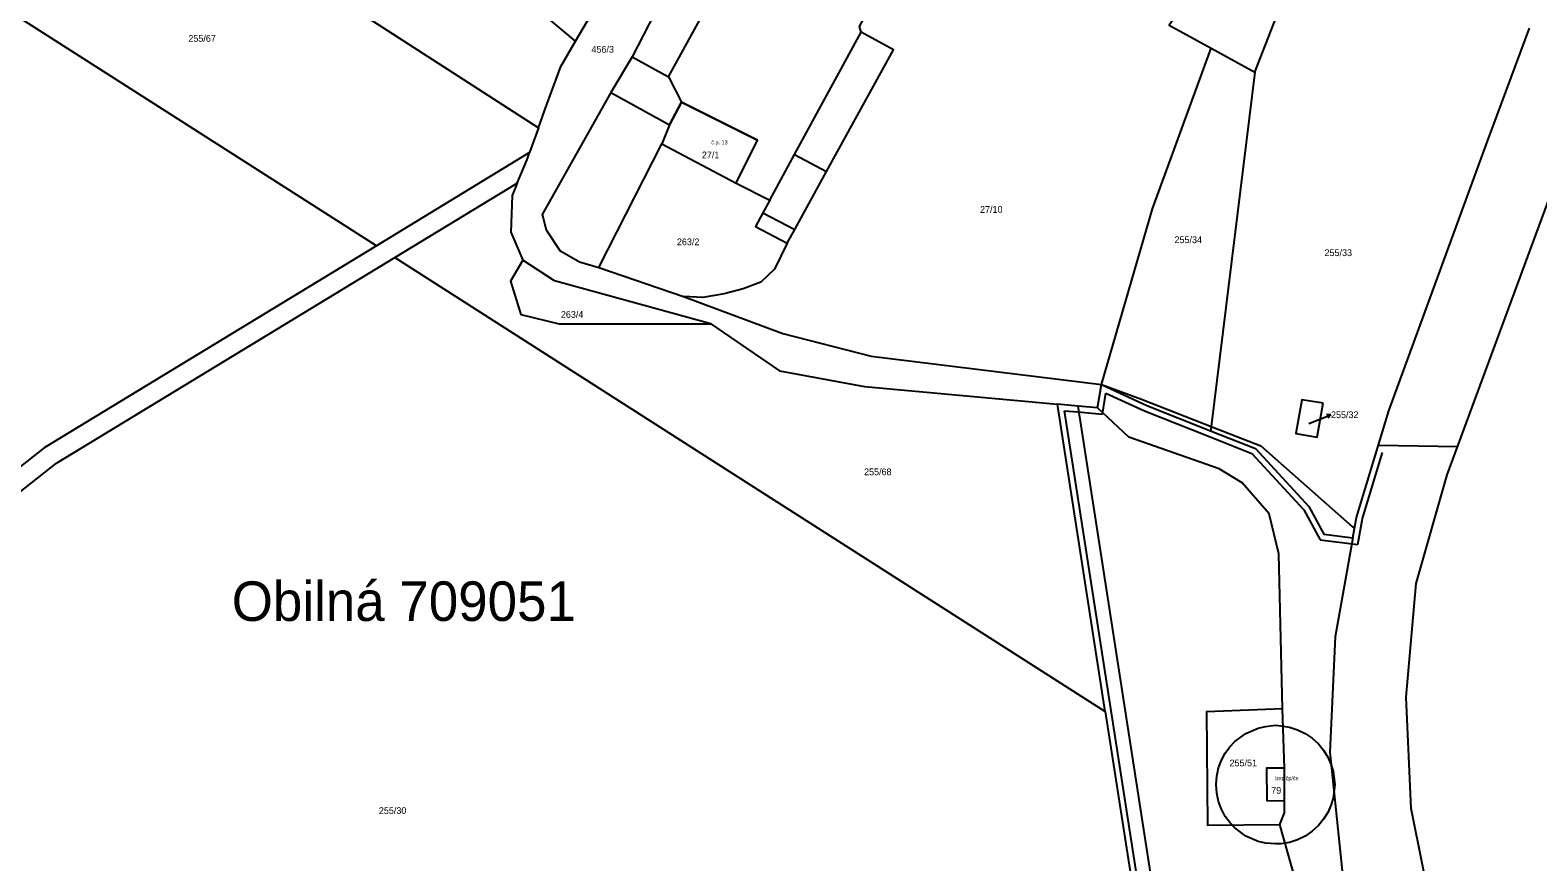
# Model space of a CAD drawing. Extents: x -882150 to -879379, y -1022570 to -1019819.
# Drawn here: x -880738 to -880356.9, y -1021575.9 to -1021365.7 of the extents above; entities that cross this region are included whole.
import ezdxf

# ---------------------------------------------------------------- set-up
doc = ezdxf.new("R2010")
doc.units = 0
for name, color, linetype in [('Definiční body', 7, 'Continuous'), ('Hranice parcel', 7, 'Continuous'), ('Parcelní čísla', 7, 'Continuous'), ('Polygon budovy', 7, 'Continuous'), ('Pop  PČ popisy', 7, 'Continuous'), ('Vnitřní kresba', 7, 'Continuous')]:
    doc.layers.add(name, color=color, linetype=linetype)

msp = doc.modelspace()

# ---------------------------------------------------------------- linework, layer by layer
at = {"layer": 'Hranice parcel'}
for p, q in [((-880600.19, -1021368.5), (-880660.06, -1021317.87)), ((-880600.19, -1021368.5), (-880583.69, -1021340.23)), ((-880428.51, -1021376.32), (-880419.38, -1021353.05)), ((-880439.53, -1021370.25), (-880428.51, -1021376.32)), ((-880428.51, -1021376.32), (-880439.5, -1021465.87)), ((-880609.55, -1021390.4), (-880611.8, -1021396.64)), ((-880611.8, -1021396.64), (-880650.52, -1021420.19)), ((-880645.83, -1021423.18), (-880614.91, -1021404.39)), ((-880468.25, -1021461.16), (-880467.26, -1021455.29)), ((-880467.26, -1021455.29), (-880455.76, -1021460.57)), ((-880473.1, -1021460.72), (-880478.38, -1021460.24)), ((-880466.28, -1021537.91), (-880478.38, -1021460.24)), ((-880468.25, -1021461.16), (-880473.1, -1021460.72)), ((-880460.36, -1021468.6), (-880468.25, -1021461.16)), ((-880455.76, -1021460.57), (-880439.64, -1021466.97)), ((-880439.5, -1021465.87), (-880439.64, -1021466.97)), ((-880403.68, -1021494.04), (-880403.27, -1021491.7)), ((-880420.99, -1021552.23), (-880421.46, -1021537.21)), ((-880421, -1021560.46), (-880420.99, -1021552.23))]:
    msp.add_line(p, q, dxfattribs=at)
for points in [[(-880383.32, -1021590.53), (-880388.97, -1021562.43), (-880390.19, -1021534.27), (-880387.73, -1021505.59), (-880379.83, -1021478.12), (-880354.56, -1021409.73), (-880325.92, -1021331.12), (-880321.65, -1021310.18), (-880321.88, -1021279.76), (-880330.68, -1021225.65), (-880330.04, -1021210.18), (-880313.87, -1021148.79), (-880301.09, -1021117.72), (-880281.33, -1021095.35), (-880255.32, -1021084.31), (-880230.68, -1021082.99), (-880217.42, -1021078.67), (-880186.94, -1021050.63), (-880171.67, -1021029), (-880165.07, -1021009.24), (-880163.83, -1020993.67)], [(-880852.86, -1021290.89), (-880665.52, -1021354.25), (-880609.55, -1021390.4)], [(-880650.52, -1021420.19), (-880751.74, -1021355.5), (-880852.86, -1021290.89)], [(-880546.66, -1021419.56), (-880544.76, -1021416.1), (-880536.71, -1021401.44), (-880519.81, -1021370.66), (-880528.01, -1021366.19), (-880528.37, -1021364.81), (-880521.3, -1021351.55), (-880551.77, -1021336.02)], [(-880427.85, -1021339.96), (-880435.17, -1021343.19), (-880450.1, -1021364.49), (-880439.53, -1021370.25)], [(-880572.87, -1021347.16), (-880585.84, -1021372.47), (-880591.22, -1021381.45)], [(-880403.27, -1021491.7), (-880402.77, -1021488.9), (-880394.62, -1021461.91), (-880369.65, -1021393.76), (-880359.04, -1021365.24)], [(-880609.55, -1021390.4), (-880608, -1021386.1), (-880603.94, -1021374.93), (-880600.19, -1021368.5)], [(-880467.26, -1021455.29), (-880454.38, -1021410.86), (-880439.53, -1021370.25)], [(-880591.22, -1021381.45), (-880608.58, -1021412.27), (-880608.35, -1021413.24), (-880607.63, -1021416.21), (-880604.16, -1021421.37), (-880599.2, -1021424.29), (-880594.31, -1021425.69), (-880572.86, -1021432.99)], [(-880591.22, -1021381.45), (-880576.42, -1021389.62), (-880578.36, -1021394.48), (-880559.6, -1021404.38), (-880551.1, -1021408.71), (-880552.81, -1021411.85), (-880554.69, -1021415.32), (-880546.66, -1021419.56)], [(-880614.91, -1021404.39), (-880612.44, -1021398.43), (-880611.8, -1021396.64)], [(-880614.91, -1021404.39), (-880616.19, -1021407.47), (-880616.55, -1021416.74), (-880613.47, -1021423.85)], [(-880650.52, -1021420.19), (-880734.5, -1021471.26), (-880791.06, -1021515.8)], [(-880546.66, -1021419.56), (-880549.89, -1021426.1), (-880553.31, -1021429.43), (-880557.81, -1021431.11), (-880562.65, -1021432.4), (-880568.03, -1021433.26), (-880572.86, -1021432.99)], [(-880872.75, -1021653.59), (-880853.95, -1021571.88), (-880731.4, -1021475.19), (-880645.83, -1021423.18)], [(-880645.83, -1021423.18), (-880556.09, -1021480.53), (-880466.28, -1021537.91)], [(-880613.47, -1021423.85), (-880616.65, -1021429.12), (-880614.04, -1021437.55), (-880604.28, -1021439.9), (-880566, -1021439.93)], [(-880566, -1021439.93), (-880605.48, -1021429.1), (-880613.47, -1021423.85)], [(-880572.86, -1021432.99), (-880547.77, -1021442.37), (-880525.48, -1021448.12), (-880467.26, -1021455.29)], [(-880566, -1021439.93), (-880548.61, -1021451.85), (-880527.16, -1021455.82), (-880478.38, -1021460.24)], [(-880533.86, -1022007.05), (-880523.29, -1021950.58), (-880522.43, -1021909.12), (-880520.53, -1021864.27), (-880518.3, -1021819.45), (-880460.57, -1021640.65), (-880455.51, -1021609.22), (-880454.71, -1021579.75), (-880473.1, -1021460.72)], [(-880411.22, -1021459.95), (-880416.58, -1021459.18), (-880418.12, -1021467.65), (-880412.75, -1021468.59), (-880411.22, -1021459.95)], [(-880421.46, -1021537.21), (-880422.44, -1021498.09), (-880424.83, -1021487.94), (-880431.68, -1021480.16), (-880437.46, -1021476.63), (-880460.36, -1021468.6)], [(-880439.64, -1021466.97), (-880428.32, -1021471.47), (-880414.85, -1021486.07), (-880411, -1021493.14), (-880403.68, -1021494.04)], [(-880403.68, -1021494.04), (-880408.13, -1021519.01), (-880409.49, -1021548.16), (-880406.41, -1021578.18), (-880397.35, -1021608.26), (-880377.39, -1021650.23), (-880346.77, -1021685.06), (-880313.96, -1021718.82), (-880296.93, -1021753.52), (-880294.62, -1021788.33), (-880298.33, -1021816.85), (-880311.6, -1021844.17), (-880330.67, -1021863.71), (-880363.25, -1021882.74), (-880382, -1021885.04)], [(-880466.28, -1021537.91), (-880459.65, -1021580.52), (-880460.51, -1021609.07), (-880465.51, -1021639.85), (-880472.9, -1021662.8)], [(-880421.46, -1021537.21), (-880440.7, -1021538.04), (-880440.47, -1021566.64), (-880422.16, -1021566.44)], [(-880420.99, -1021552.23), (-880425.55, -1021552.23), (-880425.42, -1021560.45), (-880421, -1021560.46)], [(-880422.16, -1021566.44), (-880420.98, -1021563.52), (-880421, -1021560.46)], [(-880328.46, -1021721.51), (-880371.01, -1021681.52), (-880393.83, -1021651.84), (-880414.22, -1021594.55), (-880422.16, -1021566.44)]]:
    msp.add_lwpolyline(points, dxfattribs=at)
at = {"layer": 'Polygon budovy'}
for points in [[(-880578.36, -1021394.48), (-880559.6, -1021404.38), (-880554.18, -1021393.55), (-880573.42, -1021383.9), (-880576.42, -1021389.62)], [(-880425.42, -1021560.45), (-880421, -1021560.46), (-880420.99, -1021552.23), (-880425.55, -1021552.23)]]:
    msp.add_lwpolyline(points, close=True, dxfattribs=at)
at = {"layer": 'Pop  PČ popisy'}
for p, q in [((-880414.82, -1021465.09), (-880412.03, -1021464.01)), ((-880412.03, -1021464.01), (-880409.228, -1021462.935)), ((-880409.228, -1021462.935), (-880410.343, -1021462.826)), ((-880409.228, -1021462.935), (-880409.984, -1021463.761))]:
    msp.add_line(p, q, dxfattribs=at)
at = {"layer": 'Vnitřní kresba'}
for p, q in [((-880576.66, -1021377.55), (-880562.99, -1021352.49)), ((-880544.83, -1021397.15), (-880528.01, -1021366.19)), ((-880585.84, -1021372.47), (-880576.66, -1021377.55)), ((-880576.66, -1021377.55), (-880573.42, -1021383.9)), ((-880576.42, -1021389.62), (-880573.42, -1021383.9)), ((-880573.42, -1021383.9), (-880554.18, -1021393.55)), ((-880559.6, -1021404.38), (-880554.18, -1021393.55)), ((-880594.31, -1021425.69), (-880578.36, -1021394.48)), ((-880551.1, -1021408.71), (-880544.83, -1021397.15)), ((-880544.83, -1021397.15), (-880536.71, -1021401.44)), ((-880552.81, -1021411.85), (-880544.76, -1021416.1)), ((-880467.26, -1021455.29), (-880457.12, -1021458.95)), ((-880467, -1021462.78), (-880466.11, -1021457.47)), ((-880466.11, -1021457.47), (-880456.35, -1021461.95)), ((-880458.15, -1021580.43), (-880476.6, -1021461.91)), ((-880476.6, -1021461.91), (-880473.24, -1021462.21)), ((-880473.24, -1021462.21), (-880467, -1021462.78)), ((-880457.12, -1021458.95), (-880439.5, -1021465.87)), ((-880456.35, -1021461.95), (-880440.19, -1021468.36)), ((-880439.5, -1021465.87), (-880426.93, -1021470.81)), ((-880440.19, -1021468.36), (-880429.19, -1021472.74)), ((-880429.19, -1021472.74), (-880416.08, -1021486.95)), ((-880426.93, -1021470.81), (-880403.84, -1021491.19)), ((-880401.29, -1021489.16), (-880396.24, -1021472.46)), ((-880397.23, -1021470.57), (-880377.17, -1021470.93)), ((-880416.08, -1021486.95), (-880411.95, -1021494.54)), ((-880402.45, -1021495.7), (-880401.29, -1021489.16)), ((-880403.84, -1021491.19), (-880403.27, -1021491.7)), ((-880411.95, -1021494.54), (-880402.45, -1021495.7)), ((-880430.75, -1021543.47), (-880427.6, -1021542.11)), ((-880427.6, -1021542.11), (-880425.79, -1021541.68)), ((-880425.79, -1021541.68), (-880423.24, -1021541.41)), ((-880423.24, -1021541.41), (-880421.81, -1021541.53)), ((-880421.81, -1021541.53), (-880419.75, -1021541.88)), ((-880419.75, -1021541.88), (-880417.72, -1021542.53)), ((-880417.72, -1021542.53), (-880415.78, -1021543.47)), ((-880434.79, -1021546.88), (-880433.51, -1021545.52)), ((-880433.51, -1021545.52), (-880430.75, -1021543.47)), ((-880415.78, -1021543.47), (-880414, -1021544.68)), ((-880414, -1021544.68), (-880412.42, -1021546.12)), ((-880412.42, -1021546.12), (-880411.09, -1021547.73)), ((-880437.63, -1021552.2), (-880436.9, -1021550.24)), ((-880436.9, -1021550.24), (-880435.94, -1021548.46)), ((-880435.94, -1021548.46), (-880434.79, -1021546.88)), ((-880411.09, -1021547.73), (-880410.02, -1021549.46)), ((-880410.02, -1021549.46), (-880409.22, -1021551.24)), ((-880438.08, -1021554.29), (-880437.63, -1021552.2)), ((-880409.22, -1021551.24), (-880408.69, -1021553.02)), ((-880408.69, -1021553.02), (-880408.29, -1021556.44)), ((-880438.24, -1021556.41), (-880438.08, -1021554.29)), ((-880438.08, -1021558.59), (-880438.24, -1021556.41)), ((-880408.29, -1021556.44), (-880408.69, -1021559.85)), ((-880437.63, -1021560.67), (-880438.08, -1021558.59)), ((-880436.9, -1021562.63), (-880437.63, -1021560.67)), ((-880409.22, -1021561.64), (-880410.02, -1021563.42)), ((-880408.69, -1021559.85), (-880409.22, -1021561.64)), ((-880435.94, -1021564.42), (-880436.9, -1021562.63)), ((-880434.79, -1021566), (-880435.94, -1021564.42)), ((-880411.09, -1021565.15), (-880412.42, -1021566.76)), ((-880410.02, -1021563.42), (-880411.09, -1021565.15)), ((-880433.51, -1021567.36), (-880434.79, -1021566)), ((-880430.75, -1021569.4), (-880433.51, -1021567.36)), ((-880414, -1021568.2), (-880415.78, -1021569.4)), ((-880412.42, -1021566.76), (-880414, -1021568.2)), ((-880427.6, -1021570.77), (-880430.75, -1021569.4)), ((-880425.79, -1021571.2), (-880427.6, -1021570.77)), ((-880423.24, -1021571.41), (-880425.79, -1021571.2)), ((-880421.81, -1021571.34), (-880423.24, -1021571.41)), ((-880419.75, -1021570.99), (-880421.81, -1021571.34)), ((-880417.72, -1021570.35), (-880419.75, -1021570.99)), ((-880415.78, -1021569.4), (-880417.72, -1021570.35))]:
    msp.add_line(p, q, dxfattribs=at)

# ---------------------------------------------------------------- texts
at = {"layer": 'Definiční body'}
for s, p in [('č.p. 13', (-880565.87, -1021394.57)), ('bez čp/če', (-880423.3, -1021555.28))]:
    msp.add_text(s, height=1, dxfattribs=at).set_placement(p)
at = {"layer": 'Parcelní čísla'}
for s, p in [('255/67', (-880698.05, -1021368.65)), ('456/3', (-880596.16, -1021371.42)), ('27/1', (-880568.25, -1021398.1)), ('27/10', (-880497.94, -1021411.89)), ('263/2', (-880574.56, -1021420.07)), ('255/34', (-880448.78, -1021419.54)), ('255/33', (-880410.86, -1021422.82)), ('263/4', (-880603.89, -1021438.42)), ('255/32', (-880409.23, -1021463.77)), ('255/68', (-880527.25, -1021478.2)), ('255/51', (-880434.87, -1021551.78)), ('79', (-880424.33, -1021558.71)), ('255/30', (-880649.9, -1021563.81))]:
    msp.add_text(s, height=1.7, dxfattribs=at).set_placement(p)
at = {"layer": 'Pop  PČ popisy'}
msp.add_text('Obilná 709051', height=10, dxfattribs=at).set_placement((-880687.08, -1021515.037))

doc.saveas('drawing.dxf')
